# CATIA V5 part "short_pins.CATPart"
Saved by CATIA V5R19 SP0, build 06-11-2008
Part number: short_pins
Bounding box of the stored display mesh (mm): x -10 to 10, y -10 to 10, z -40 to 0
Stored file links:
  D:\VKW\Work\Process_And_Tools\Courseware_Development\Tangix_Certification_Project\Preparation_Kit\CATIA V5 Associate_Preparation kit\R19_Data\Chain Link Assembly\short_pins.CATPart
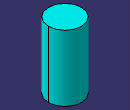
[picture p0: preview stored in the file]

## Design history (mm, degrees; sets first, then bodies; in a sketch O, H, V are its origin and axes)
Body1 (main body)
  Sketch1 on xy-plane, origin (0, 0, 0), H (1, 0, 0), V (0, 1, 0)
    circle A1 centre (0, 0) radius 10
    radius A1 = 10
  Pad1: profile Sketch1, direction (0, 0, -1), length 40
